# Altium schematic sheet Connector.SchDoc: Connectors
size A4; Organization: Trenz Electronic GmbH; DocumentNumber: TE0304 - Demo Baseboard; Revision: 00; SheetNumber: 3; SheetTotal: 4; Date: 2009-04-16
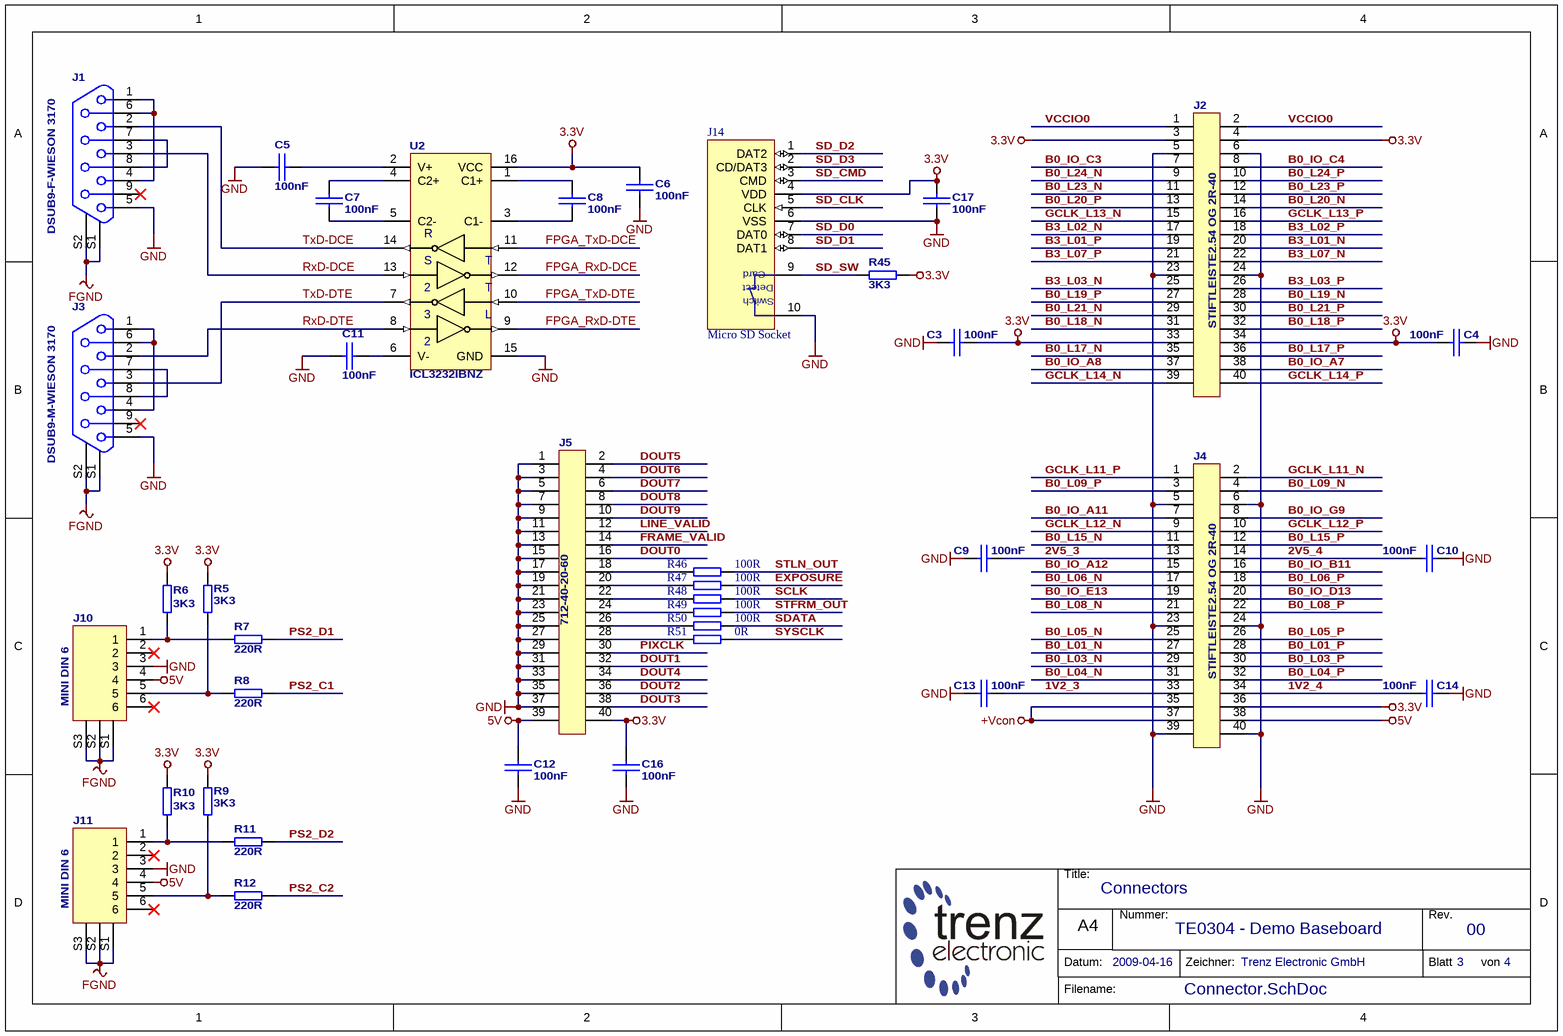
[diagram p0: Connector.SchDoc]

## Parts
C3  100nF  [CAPC1608N]
C4  100nF  [CAPC1608N]
C5  100nF  [CAPC1608N]
C6  100nF  [CAPC1608N]
C7  100nF  [CAPC1608N]
C8  100nF  [CAPC1608N]
C9  100nF  [CAPC1608N]
C10  100nF  [CAPC1608N]
C11  100nF  [CAPC1608N]
C12  100nF  [CAPC1608N]
C13  100nF  [CAPC1608N]
C14  100nF  [CAPC1608N]
C16  100nF  [CAPC1608N]
C17  100nF  [CAPC1608N]
J1  DSUB9-F-WIESON 3170  [WIESON 3170-9F]
J2  STIFTLEISTE2.54 OG 2R-40  [STIFTLEISTE2_54 OG 2R-40]
J3  DSUB9-M-WIESON 3170  [WIESON 3170-9M]
J4  STIFTLEISTE2.54 OG 2R-40  [STIFTLEISTE2_54 OG 2R-40]
J5  712-40-20-60  [712-40-20-60]
J10  MINI DIN 6  [MINI DIN 6]
J11  MINI DIN 6  [MINI DIN 6]
J14  Micro SD Socket  [112A-TXAR-R01]
R5  3K3  [RESC1609N]
R6  3K3  [RESC1609N]
R7  220R  [RESC1609N]
R8  220R  [RESC1609N]
R9  3K3  [RESC1609N]
R10  3K3  [RESC1609N]
R11  220R  [RESC1609N]
R12  220R  [RESC1609N]
R45  3K3  [RESC1609N]
R46  100R  [RESC1609N]
R47  100R  [RESC1609N]
R48  100R  [RESC1609N]
R49  100R  [RESC1609N]
R50  100R  [RESC1609N]
R51  0R  [RESC1609N]
U2  ICL3232IBNZ  [SOIC127P600X175-16N]

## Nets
3.3V: C3.1 C4.1 C6.1 C16.1 C17.1 J2.3 J2.4 J2.33 J2.34 J4.36 J5.40 J14.4(VDD) R5.1 R6.1 R9.1 R10.1 R45.2 U2.16(VCC)
5V: C12.1 J4.38 J5.39 J10.4 J11.4
+Vcon: J4.35 J4.37
FGND: J1.S1 J1.S2 J3.S1 J3.S2 J10.S1 J10.S2 J10.S3 J11.S1 J11.S2 J11.S3
GND: C3.2 C4.2 C5.2 C6.2 C9.2 C10.2 C11.2 C12.2 C13.2 C14.2 C16.2 C17.2 J1.5 J2.5 J2.6 J2.23 J2.24 J3.5 J4.5 J4.6 J4.23 J4.24 J4.39 J4.40 J5.1 J5.3 J5.5 J5.7 J5.9 J5.11 J5.13 J5.15 J5.17 J5.19 J5.21 J5.23 J5.25 J5.27 J5.29 J5.31 J5.33 J5.35 J5.37 J10.3 J11.3 J14.6(VSS) J14.10 U2.15(GND)
1V2_3: C13.1 J4.33
1V2_4: C14.1 J4.34
2V5_3: C9.1 J4.13
2V5_4: C10.1 J4.14
B0_IO_A7: J2.38
B0_IO_A8: J2.37
B0_IO_A11: J4.7
B0_IO_A12: J4.15
B0_IO_B11: J4.16
B0_IO_C3: J2.7
B0_IO_C4: J2.8
B0_IO_D13: J4.20
B0_IO_E13: J4.19
B0_IO_G9: J4.8
B0_L01_N: J4.27
B0_L01_P: J4.28
B0_L03_N: J4.29
B0_L03_P: J4.30
B0_L04_N: J4.31
B0_L04_P: J4.32
B0_L05_N: J4.25
B0_L05_P: J4.26
B0_L06_N: J4.17
B0_L06_P: J4.18
B0_L08_N: J4.21
B0_L08_P: J4.22
B0_L09_N: J4.4
B0_L09_P: J4.3
B0_L15_N: J4.11
B0_L15_P: J4.12
B0_L17_N: J2.35
B0_L17_P: J2.36
B0_L18_N: J2.31
B0_L18_P: J2.32
B0_L19_N: J2.28
B0_L19_P: J2.27
B0_L20_N: J2.14
B0_L20_P: J2.13
B0_L21_N: J2.29
B0_L21_P: J2.30
B0_L23_N: J2.11
B0_L23_P: J2.12
B0_L24_N: J2.9
B0_L24_P: J2.10
B3_L01_N: J2.20
B3_L01_P: J2.19
B3_L02_N: J2.17
B3_L02_P: J2.18
B3_L03_N: J2.25
B3_L03_P: J2.26
B3_L07_N: J2.22
B3_L07_P: J2.21
DOUT0: J5.16
DOUT1: J5.32
DOUT2: J5.36
DOUT3: J5.38
DOUT4: J5.34
DOUT5: J5.2
DOUT6: J5.4
DOUT7: J5.6
DOUT8: J5.8
DOUT9: J5.10
EXPOSURE: R47.2
FPGA_RxD-DCE: U2.12(R1O)
FPGA_RxD-DTE: U2.9(R2O)
FPGA_TxD-DCE: U2.11(T1I)
FPGA_TxD-DTE: U2.10(T2I)
FRAME_VALID: J5.14
GCLK_L11_N: J4.2
GCLK_L11_P: J4.1
GCLK_L12_N: J4.9
GCLK_L12_P: J4.10
GCLK_L13_N: J2.15
GCLK_L13_P: J2.16
GCLK_L14_N: J2.39
GCLK_L14_P: J2.40
LINE_VALID: J5.12
PIXCLK: J5.30
PS2_C1: R8.2
PS2_C2: R12.2
PS2_D1: R7.2
PS2_D2: R11.2
RxD-DCE: J1.3 U2.13(R1I)
RxD-DTE: J3.2 U2.8(R2I)
SCLK: R48.2
SD_CLK: J14.5(CLK)
SD_CMD: J14.3(CMD)
SD_D0: J14.7(DAT0)
SD_D1: J14.8(DAT1)
SD_D2: J14.1(DAT2)
SD_D3: J14.2(CD/DAT3)
SD_SW: J14.9 R45.1
SDATA: R50.2
STFRM_OUT: R49.2
STLN_OUT: R46.2
SYSCLK: R51.2
TxD-DCE: J1.2 U2.14(T1O)
TxD-DTE: J3.3 U2.7(T2O)
VCCIO0: J2.1 J2.2
NetC5_1: C5.1 U2.2(V+)
NetC7_1: C7.1 U2.4(C2+)
NetC7_2: C7.2 U2.5(C2-)
NetC8_1: C8.1 U2.1(C1+)
NetC8_2: C8.2 U2.3(C1-)
NetC11_1: C11.1 U2.6(V-)
NetJ1_1: J1.1 J1.4 J1.6
NetJ1_7: J1.7 J1.8
NetJ3_1: J3.1 J3.4 J3.6
NetJ3_7: J3.7 J3.8
NetJ5_18: J5.18 R46.1
NetJ5_20: J5.20 R47.1
NetJ5_22: J5.22 R48.1
NetJ5_24: J5.24 R49.1
NetJ5_26: J5.26 R50.1
NetJ5_28: J5.28 R51.1
NetJ10_1: J10.1 R6.2 R7.1
NetJ10_5: J10.5 R5.2 R8.1
NetJ11_1: J11.1 R10.2 R11.1
NetJ11_5: J11.5 R9.2 R12.1

Not connected (* = marked no-connect by the designer): J1 9*; J3 9*; J10 2* 6*; J11 2* 6*

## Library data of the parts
C3-C14 C16 C17 = 21382: AN: 21382; Bezeichnung: KON 100nF 16V X7R SMD; Param 1: 16V; Param 2: X7R; Value: 100n
J1 = 22388: DSUB 9 Female US Kurz 90° Einlöt; AN: 22388; Bezeichnung: STE DSUB 9pol Buchse 90° WIESON3170
J2 J4 = 22320: AN: 22320; Bezeichnung: Stiftleiste gerade 2-reihig, 40pol
J3 = 22390: DSUB 9 Male US Kurz 90° Einlöt; AN: 22390; Bezeichnung: STE DSUB 9pol Stecker 90° WIESON3170
J5 = 23184: AN: 23184; Bezeichnung: Stiftleiste 2-reihig, 40pol
J10 J11 = 22383: PS/2; AN: 22383; Bezeichnung: STE Mini DIN Buchse 6 polig
J14 = 23193: AN: 23193
R5 R6 R9 R10 R45 = 22433: AN: 22433; Bezeichnung: WID SMD 3K3 1% 0,1W; Value: 3.3K
R7 R8 R11 R12 = 22324: AN: 22324; Bezeichnung: WID SMD 220R 1% 0,1W; Value: 220
R46-R50 = 21380: AN: 21380; Bezeichnung: WID SMD 100R 1% 0,1W; Value: 100
R51 = 21491: AN: 21491; Bezeichnung: WID SMD 0R; Value: 0
U2 = 22710: 3.3VV RS232 Dual Driver / Receiver 0,1µF; AN: 22710; Bezeichnung: ICL3232IBNZ SO16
